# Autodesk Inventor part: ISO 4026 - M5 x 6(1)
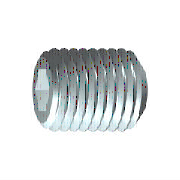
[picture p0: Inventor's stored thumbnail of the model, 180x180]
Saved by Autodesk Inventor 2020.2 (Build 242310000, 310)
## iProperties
Created: 2019-01
Part Number: ISO 4026 - M5 x 6(1)
Material: Edelstahl, 440C
Description: Innensechskant-Gewindestifte mit Kegelstumpf
Document SubType Name: Modeling
Standard: ISO 4026
Designer: lutzd
Standard Revision: Third edition 2003-12-01
Standards Organization: ISO
Language: de-DE
Size Designation: M5 x 6
Categories: <MemberInstance><Categories><Category DisplayName="Verbindungselemente" InternalName="e4da775c-781d-43d5-af7c-5136215cf5a6" Mnemonic="FSTN"><Category DisplayNam
Mass: 0.746076 g
Surface Area: 1.51313 cm^2
Volume: 0.0962679 cm^3
Density: 7.75 g/cm^3
Appearance: Semi-Polished(3)
IsCustomPart: 0
Author: lutzd
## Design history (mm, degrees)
sketch "Skizze1"
  geometry: L1 (0, 0)-(2.167, 0); L2 (6, 1.443)-(6, 2.5); L3 (6, 2.5)-(0, 2.5); L4 (6, 1.443)-(3, 1.443); L5 (3, 1.443)-(2.167, 0); L6 (0, -0.5)-(0, 3) reference; L7 (0, 2.5)-(0, 0)
  constraints: 13 end point, 3 parallel, 1 collinear, 1 perpendicular, 1 point on line
  dimensions: "d0" = 3 distance of L2.start L4.end (= INTI); "d1" = 60 deg angle of L5 L1; "d2" = 5 diameter of L3 L1 (= NND); "d3" = 2.88675 diameter of L4 L1 (= 1.1547 x SW); "d5" = 6 distance from line of L2 L3.end (= NLG)
revolve "Körper" sketch "Skizze1" stored, may be unused: angle "d6" = 90 deg
sketch "Skizze2"
  geometry: L1 (-0.722, 1.25)-(0.722, 1.25); L2 (0.722, 1.25)-(1.443, 0); L3 (1.443, 0)-(0.722, -1.25); L4 (0.722, -1.25)-(-0.722, -1.25); L5 (-0.722, -1.25)-(-1.443, 0); L6 (-1.443, 0)-(-0.722, 1.25); A1 r 1.443 centre (0, 0) between (-0.722, 1.25) and (0.722, 1.25) reference; 2 further points
  constraints: 12 end point, 2 point on circle, 1 coincident, 1 horizontal, 11 other
extrude "Loch" join sketch "Skizze2" taper "d9" = 0 deg; stored distance "d21" = 10
workaxis "Work Axis1"
workplane "Work Plane1"
body "Solid1"
chamfer "Fase1" distance "d7" = 0.49076 (= -0.5 x GD1 + 0.5 x NND); stored, may be unused: angle "d8" = 45 deg (= FAWI), second distance "d29" = 0.49076 (= -0.5 x GD1 + 0.5 x NND)
feature "Gewinde" dims "d11" = 6 (= NLG), "d12" = 0
chamfer "Fase2" distance "d13" = 0.49076 (= -0.5 x GD1 + 0.5 x NND); stored, may be unused: angle "d14" = 45 deg (= FAWI), second distance "d30" = 0.49076 (= -0.5 x GD1 + 0.5 x NND)
other parameters: "NND" = 5 [user parameter; used in 5 equation terms], "NLG" = 6 [user parameter; used in 2 equation terms], "INTI" = 3 [user parameter; used in 1 equation term], "FAWI" = 45 deg [user parameter; used in 2 equation terms], "SW" = 2.5 [user parameter; used in 2 equation terms], "GD1" = 4.01848 (= THREADDIA - 1.2269 x PTC) [user parameter; used in 4 equation terms], "d4" = 0, "FAWI1" = 45 deg [user parameter], "d15" = 0, "d31" = 0, "GUL" = 0.49076 (= 0.61345 x PTC) [user parameter], "SPD" = 3.5 [user parameter], "SEWI" = 90 deg [user parameter], "TOA" = 30 deg [user parameter], "THREADDIA" = 5 [user parameter; used in 1 equation term], "TPU" = 12.5 (computed from PTC) [user parameter], "PTC" = 0.8 [user parameter; used in 4 equation terms], "GAL" = 0.49076 (= 0.61345 x PTC) [user parameter], "E0" = 2.8875 (= 1.155 x SW) [user parameter]
